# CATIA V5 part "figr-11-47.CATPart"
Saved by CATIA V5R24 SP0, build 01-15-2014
Part number: Part1
Bounding box of the stored display mesh (mm): x -171.181 to 0, y -220 to 0, z -11.432 to 46.691
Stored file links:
  D:\KAVITA\CATIA V5-6R2014 Project_ Kavita\CATIA V5-6R2014_partfiles\Partfiles\c11_catia_v5-6r2014_prt\figr-11-47.CATPart
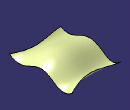
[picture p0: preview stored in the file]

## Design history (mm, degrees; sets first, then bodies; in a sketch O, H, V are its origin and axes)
Set1
  Sweep1: type Unspec, Profile Sketch2, Guide Sketch1
Body1 (main body)
  Sketch1 on yz-plane, origin (0, 0, 0), H (0, 1, 0), V (0, 0, 1)
    spline S1 through (0, 0) (-40, -10) (-100, 20) (-170, 0) (-220, 10)
    point P1 (0, 0)
    coincidence: P1 O
  Sketch2 on zx-plane, origin (0, 0, 0), H (-1, 0, 0), V (0, 0, 1)
    spline S1 through (0, 0) (60, 30) (121.1814, 19.9844) (171.1814, 9.9844)
    point P1 (0, 0)
    coincidence: P1 O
